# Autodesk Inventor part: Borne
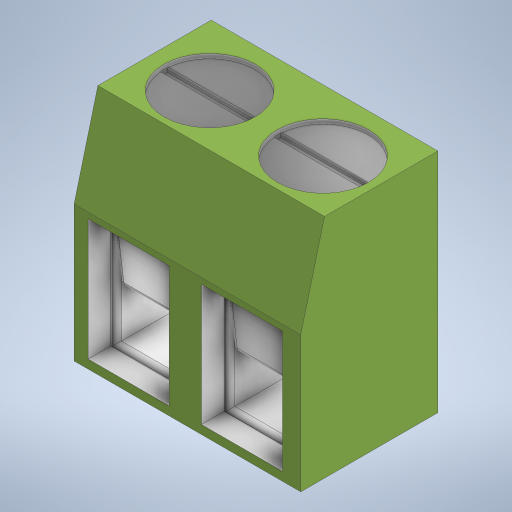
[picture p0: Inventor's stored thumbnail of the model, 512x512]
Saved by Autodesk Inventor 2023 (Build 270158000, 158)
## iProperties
Created: 2025-02
Part Number: Borne
Material: Générique
Document SubType Name: Modeling
Designer: bruno
Density: 1 g/cm^3
Appearance: Par défaut
Author: bruno
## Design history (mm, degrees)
sketch "Esquisse1"
  geometry: L1 (0, 0)-(6, 0); L2 (0, -6.049)-(0, 0); L3 (6, 0)-(10, -1.049); L4 (10, -1.049)-(10, -6.049); L5 (10, -6.049)-(0, -6.049); L6 (6, 0)-(6, -6.049)
  constraints: 12 end point, 2 perpendicular, 1 horizontal, 1 parallel, 1 point on line, 1 vertical
  dimensions: "d4" = 10 distance between parallel lines of L2 L4
extrude "Extrusion1" new body sketch "Esquisse1" distance "d5" = 10; taper "d6" = 0 deg
sketch "Esquisse4"
  geometry: L1 (0.75, 6.951)-(4.569, 6.951) reference; L2 (0.75, 6.951)-(0.75, 5.951) reference; L3 (4.569, 6.951)-(4.569, 5.951) reference; L4 (5.75, 6.951)-(9.569, 6.951) reference; L5 (5.75, 6.951)-(5.75, 5.951) reference; L6 (9.569, 6.951)-(9.569, 5.951) reference; L7 (10.75, 6.951)-(14.569, 6.951) reference; L8 (10.75, 6.951)-(10.75, 4.951) reference; L9 (10.75, 4.951)-(14.569, 4.951) reference; L10 (14.569, 6.951)-(14.569, 4.951) reference; L11 (2.66, 4.951)-(2.66, -0.409); L12 (9.569, 5.951)-(5.75, 5.951) reference; L13 (4.569, 5.951)-(0.75, 5.951) reference; C1 r 2.012 at (2.66, 2.271); 1 further point
  constraints: 2 end point, 1 centre point, 1 midpoint, 1 vertical
extrude "Extrusion4" cut sketch "Esquisse4" distance "d14" = 0.2; taper "d15" = 0 deg
sketch "Esquisse5"
  geometry: L1 (-2.052, -0.162)-(2.168, -0.162); L2 (2.168, -0.162)-(2.168, 0.18); L3 (2.168, 0.18)-(-2.052, 0.18); L4 (-2.052, 0.18)-(-2.052, -0.162); 1 further point
  constraints: 8 end point, 2 parallel, 1 horizontal, 1 perpendicular
extrude "Extrusion5" cut sketch "Esquisse5" distance "d16" = 0.2; taper "d17" = 0 deg
pattern_linear "Réseau rectangulaire2" dims "d20" = 5
sketch "Esquisse6"
  geometry: L1 (0.622, 5.74)-(4.192, 5.74); L2 (4.192, 5.74)-(4.192, 0.384); L3 (4.192, 0.384)-(0.622, 0.384); L4 (0.622, 0.384)-(0.622, 5.74); 1 further point
  constraints: 8 end point, 2 parallel, 1 horizontal, 1 perpendicular
extrude "Extrusion6" cut sketch "Esquisse6" distance "d21" = 4; taper "d22" = 0 deg
sketch "Esquisse7"
  geometry: L1 (0.622, 0.384)-(0.622, 5.74) reference; L2 (4.192, 5.74)-(4.192, 0.384) reference; L3 (0.622, 5.74)-(4.192, 5.74); L4 (4.192, 5.74)-(4.192, 0.384); L5 (4.192, 0.384)-(0.622, 0.384); L6 (0.622, 0.384)-(0.622, 5.74); L7 (0.893, 5.469)-(3.899, 5.469); L8 (3.899, 5.469)-(3.899, 0.61); L9 (3.899, 0.61)-(0.893, 0.61); L10 (0.893, 0.61)-(0.893, 5.469); L11 (0.622, 5.74)-(4.192, 5.74) reference; L12 (0.622, 5.74)-(1.021, 2.893); L13 (1.021, 2.893)-(3.739, 2.893); L14 (3.739, 2.893)-(4.192, 5.74); 5 further points
  constraints: 22 end point, 5 parallel, 2 horizontal, 2 perpendicular
extrude "Extrusion7" join sketch "Esquisse7" distance "d26" = 3; taper "d27" = 0 deg
fillet "Congé1" dims "d28" = 0.2
pattern_linear "Réseau rectangulaire3" dims "d25" = 5
node "Solide1"
